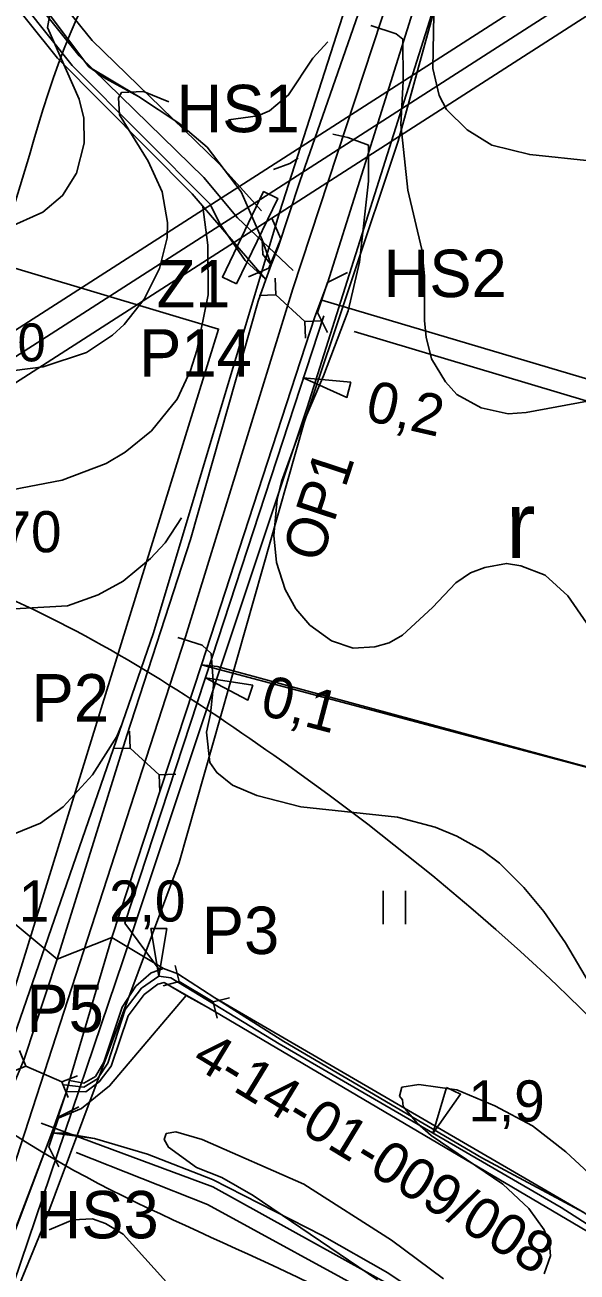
# Model space of a CAD drawing. Extents: x -684583 to -680383, y -1157874 to -1154904.
# Drawn here: x -682753.2 to -682578.4, y -1156107.3 to -1155712.7 of the extents above; entities that cross this region are included whole.
import ezdxf

# ---------------------------------------------------------------- set-up
doc = ezdxf.new("R2010")
doc.units = 0
for name, color, linetype in [('01_DOPRAVA', 7, 'Continuous'), ('01_VRSTEVNICE', 7, 'Continuous'), ('02_KULTURY STAV', 7, 'Continuous'), ('03_PC_NÁVRH', 7, 'Continuous'), ('03_PC_OBJEKTY_NÁVRH', 7, 'Continuous'), ('03_PC_OBJEKTY_STAV', 7, 'Continuous'), ('03_PC_STAV', 7, 'Continuous'), ('05_VHO_MELIORACE', 7, 'Continuous'), ('05_VHO_PŘÍKOP_NÁVRH', 7, 'Continuous'), ('05_VHO_V_TOK', 7, 'Continuous'), ('06_BIOGEOGRAFIE', 7, 'Continuous'), ('06_ÚSES_IP', 7, 'Continuous'), ('07_ELEKTRO', 7, 'Continuous'), ('07_OCH_P A POPISY TI', 7, 'Continuous')]:
    doc.layers.add(name, color=color, linetype=linetype)

msp = doc.modelspace()

# ---------------------------------------------------------------- linework, layer by layer
at = {"layer": '01_DOPRAVA'}
msp.add_lwpolyline([(-682444.78, -1155001.44), (-682484.97, -1155081.41), (-682523.81, -1155212.27), (-682554.69, -1155333.36), (-682575.58, -1155465.36), (-682603.29, -1155587.36), (-682620.55, -1155650.97), (-682668.34, -1155796.22), (-682702.3, -1155906.34), (-682764.53, -1156097.63), (-682782.62, -1156147.93)], dxfattribs=at)
at = {"layer": '01_VRSTEVNICE'}
for points in [[(-682382.21, -1155809.3), (-682389.33, -1155809.04), (-682397.32, -1155806.76), (-682406.03, -1155802.05), (-682410.45, -1155798.77), (-682430.27, -1155780.8), (-682439.26, -1155774.38), (-682444.11, -1155771.67), (-682453.53, -1155768.39), (-682461.51, -1155767.53), (-682469.5, -1155768.1), (-682506.59, -1155773.81), (-682523.13, -1155773.24), (-682535.12, -1155769.96), (-682551.95, -1155762.25), (-682565.36, -1155757.69), (-682573.35, -1155755.83), (-682593.32, -1155753.7), (-682605.3, -1155750.7), (-682613.14, -1155745.85), (-682619.7, -1155739.43), (-682621.99, -1155735.01), (-682623.98, -1155726.45), (-682623.41, -1155691.93)], [(-682985.16, -1155828.73), (-682971.04, -1155827.87), (-682959.05, -1155826.3), (-682925.39, -1155819.46), (-682916.83, -1155817.03), (-682906.56, -1155813.18), (-682896.29, -1155808.19), (-682880.89, -1155802.34), (-682838.09, -1155789.07), (-682808.99, -1155783.08), (-682772.76, -1155779.8), (-682758.78, -1155776.95), (-682747.51, -1155771.95), (-682741.24, -1155766.68), (-682736.82, -1155759.54), (-682734.39, -1155750.13), (-682734.53, -1155742.14), (-682735.96, -1155736.15), (-682746.07, -1155713.51), (-682745.09, -1155708.19)], [(-682643.67, -1155712.9), (-682635.68, -1155715.47), (-682633.54, -1155717.18), (-682633.4, -1155730.45), (-682634.11, -1155744.14), (-682631.97, -1155764.96), (-682627.55, -1155783.79), (-682626.69, -1155792.07), (-682626.69, -1155806.33), (-682626.12, -1155811.47), (-682624.41, -1155818.31), (-682619.99, -1155825.59), (-682616.42, -1155829.58), (-682608.72, -1155833.86), (-682600.16, -1155835.72), (-682594.46, -1155835.29), (-682575.06, -1155831.72)], [(-682657.28, -1155718.07), (-682662.01, -1155723.22), (-682669.72, -1155734.85), (-682675.76, -1155739.86), (-682679.47, -1155741.43), (-682688.74, -1155742.71)], [(-682707.57, -1155737.05), (-682715.6, -1155733.76), (-682722.55, -1155734.01), (-682723.55, -1155735.72), (-682723.26, -1155741.14), (-682714.14, -1155755.84), (-682709.71, -1155765.54), (-682708, -1155775.24), (-682708.14, -1155780.08), (-682710.57, -1155789.78), (-682715.42, -1155799.48), (-682721.7, -1155807.47), (-682725.4, -1155810.9), (-682733.68, -1155816.32), (-682747.37, -1155820.88), (-682756.5, -1155822.02)], [(-682655.65, -1155747.28), (-682650.94, -1155748.28), (-682644.38, -1155750.7), (-682644.38, -1155762.11), (-682647.23, -1155787.79), (-682650.8, -1155803.19), (-682658.65, -1155823.73), (-682666.35, -1155841.71), (-682671.91, -1155857.11), (-682673.34, -1155862.82), (-682674.34, -1155874.23), (-682673.48, -1155882.79), (-682670.77, -1155891.35), (-682667.35, -1155897.48), (-682662.93, -1155902.62), (-682656.08, -1155907.61), (-682649.23, -1155909.89), (-682642.39, -1155909.46), (-682637.82, -1155908.18), (-682633.68, -1155905.75), (-682624.13, -1155897.05), (-682616.71, -1155889.21), (-682612.15, -1155886.07), (-682607.58, -1155884.36), (-682600.73, -1155883.07), (-682596.17, -1155883.79), (-682588.47, -1155886.78), (-682581.33, -1155893.34), (-682575.34, -1155901.9)], [(-682666.67, -1155754.8), (-682669.34, -1155756.55), (-682674.48, -1155758.4)], [(-682757.36, -1155859.82), (-682741.38, -1155856.68), (-682727.4, -1155851.41), (-682721.41, -1155847.84), (-682713.14, -1155841.14), (-682705.01, -1155831.15), (-682700.73, -1155822.02), (-682698.73, -1155815.75), (-682695.16, -1155798.06), (-682695.31, -1155782.37), (-682696.88, -1155770.24)], [(-682862.77, -1155969.37), (-682865.91, -1155959.82), (-682870.76, -1155950.69), (-682885.88, -1155927.29), (-682908.84, -1155897.62), (-682911.55, -1155892.2), (-682911.55, -1155890.63), (-682910.7, -1155890.63), (-682910.56, -1155889.78), (-682891.16, -1155891.21), (-682875.47, -1155893.34), (-682852.93, -1155897.91), (-682834.1, -1155903.04), (-682825.54, -1155904.33), (-682809.56, -1155905.33), (-682793.59, -1155904.47), (-682787.88, -1155903.61), (-682767.91, -1155898.05), (-682739.67, -1155896.48), (-682729.97, -1155893.06), (-682722.12, -1155888.64), (-682713.42, -1155881.5), (-682708.82, -1155876.58), (-682703.58, -1155868.67)], [(-682704.72, -1155906.47), (-682697.02, -1155908.89), (-682694.17, -1155911.6), (-682693.45, -1155921.59), (-682694.45, -1155930.72), (-682695.73, -1155936.42), (-682694.59, -1155946.12), (-682692.45, -1155949.26), (-682687.46, -1155953.25), (-682679.76, -1155956.53), (-682665.78, -1155960.1), (-682635.25, -1155963.38), (-682623.27, -1155966.52), (-682616.42, -1155969.37), (-682608.29, -1155973.94), (-682602.87, -1155977.93), (-682595.17, -1155985.63), (-682588.89, -1155993.2), (-682582.05, -1156003.18), (-682561.93, -1156037.13)], [(-682763.92, -1156063.23), (-682764.06, -1156057.96), (-682766.06, -1156044.26), (-682769.62, -1156032.85), (-682773.76, -1156023.72), (-682787.31, -1156000.9), (-682797.01, -1155982.78), (-682797.15, -1155979.22), (-682791.31, -1155981.93), (-682785.17, -1155983.35), (-682781.18, -1155981.5), (-682778.18, -1155975.36), (-682778.47, -1155968.66), (-682779.32, -1155966.81), (-682779.85, -1155960.09), (-682769.48, -1155967.38), (-682763.92, -1155969.23), (-682756.79, -1155968.8), (-682748.23, -1155965.24), (-682741.09, -1155960.1), (-682731.82, -1155949.97), (-682724.12, -1155937.85), (-682722.55, -1155934.28)], [(-682588.75, -1156107.88), (-682586.75, -1156102.17), (-682587.04, -1156098.47), (-682588.75, -1156093.9), (-682593.6, -1156087.2), (-682601.88, -1156079.49), (-682624.55, -1156064.09), (-682628.98, -1156060.24), (-682633.4, -1156054.96), (-682633.68, -1156052.82), (-682634.54, -1156051.68), (-682633.83, -1156048.83), (-682628.41, -1156047.97), (-682616.42, -1156049.68), (-682604.44, -1156054.67), (-682592.46, -1156061.09), (-682581.9, -1156069.22), (-682561.65, -1156088.05)], [(-682641.53, -1156109.73), (-682680.9, -1156083.06), (-682690.88, -1156077.35), (-682698.87, -1156074.22), (-682707.72, -1156067.8), (-682709.14, -1156065.37), (-682708.43, -1156063.52), (-682705.43, -1156062.95), (-682697.02, -1156065.37), (-682664.92, -1156079.49), (-682637.11, -1156097.18), (-682620.7, -1156109.45)], [(-682745.52, -1156093.9), (-682737.96, -1156090.76), (-682731.82, -1156090.48), (-682727.69, -1156091.9), (-682722.12, -1156095.33), (-682705.43, -1156113.73), (-682691.17, -1156131.28), (-682682.47, -1156143.26), (-682670.49, -1156161.66), (-682629.69, -1156229.13), (-682597.45, -1156287.18), (-682585.33, -1156306.3), (-682572.83, -1156324.37)]]:
    msp.add_lwpolyline(points, dxfattribs=at)
at = {"layer": '02_KULTURY STAV'}
for points in [[(-682742.95, -1156008.33), (-682720.91, -1155937.51), (-682700.78, -1155875.54), (-682679.31, -1155800.06), (-682676.88, -1155793.28), (-682675.23, -1155788.62), (-682672.99, -1155782.95), (-682666.12, -1155762.26), (-682647.64, -1155709.29), (-682624.39, -1155632.23), (-682608.85, -1155568.57), (-682588.52, -1155559.14), (-682606.64, -1155634.44), (-682625.87, -1155693.99), (-682647.1, -1155761.89), (-682657.41, -1155794.38), (-682661.35, -1155805), (-682697.27, -1155915.21), (-682725.67, -1156001.43)], [(-682692.35, -1155915.71), (-682546.41, -1155955.28), (-682554.4, -1155990.65), (-682555.92, -1156043.51), (-682562.23, -1156060.24), (-682562.06, -1156068.8), (-682556.56, -1156078.19), (-682554.09, -1156081.55), (-682562.72, -1156088), (-682571.24, -1156092.01), (-682576.25, -1156088.48), (-682608.5, -1156071.15), (-682671.25, -1156034.36), (-682693.08, -1156020.51), (-682704.73, -1156012.95), (-682709.29, -1156011.25), (-682725.67, -1156001.43), (-682697.27, -1155915.21)], [(-682725.67, -1156001.43), (-682709.29, -1156011.25), (-682713.21, -1156012.6), (-682718.03, -1156016.89), (-682722.37, -1156023.45), (-682728.14, -1156040.85), (-682730.88, -1156045.44), (-682734.55, -1156047.54), (-682739.11, -1156046.65)], [(-682740.04, -1156050.18), (-682733.84, -1156050.25), (-682729.64, -1156047.08), (-682725.87, -1156042.18), (-682720.5, -1156026.23), (-682715.37, -1156019.5), (-682711.09, -1156016.18), (-682709.08, -1156015.71), (-682702.07, -1156019.82), (-682726.38, -1156048.39), (-682735.27, -1156055.51), (-682742.82, -1156058.77)]]:
    msp.add_lwpolyline(points, close=True, dxfattribs=at)
for points in [[(-682790.82, -1155659.69), (-682738.18, -1155725.49), (-682694.52, -1155769.41), (-682691.48, -1155775.66), (-682683.47, -1155787.27), (-682676.88, -1155793.28), (-682675.23, -1155788.62), (-682678.08, -1155780.69), (-682684.73, -1155765.47), (-682695.46, -1155751.36), (-682704.47, -1155743.75), (-682717.26, -1155735.33), (-682727.64, -1155729.6), (-682732.92, -1155725.98), (-682761.91, -1155687.44)], [(-682790.82, -1155659.69), (-682738.18, -1155725.49), (-682694.52, -1155769.41), (-682691.48, -1155775.66), (-682683.47, -1155787.27), (-682676.88, -1155793.28), (-682679.31, -1155800.06), (-682700.78, -1155875.54), (-682720.91, -1155937.51), (-682742.95, -1156008.33), (-682780.55, -1155977.07)], [(-682415.34, -1155677.48), (-682425.43, -1155731.81), (-682370.95, -1155762.69), (-682382.94, -1155812.42), (-682392.09, -1155851.75), (-682394.33, -1155862.14), (-682395.58, -1155865.96), (-682409.73, -1155861.86), (-682426.71, -1155857.66), (-682455.64, -1155852.31), (-682472.04, -1155850.36), (-682483.37, -1155850.15), (-682508.9, -1155844.44), (-682515.71, -1155860.72), (-682519, -1155873.01), (-682541.61, -1155930.68), (-682546.41, -1155955.28), (-682697.27, -1155915.21), (-682661.35, -1155805), (-682657.41, -1155794.38), (-682647.1, -1155761.89), (-682625.87, -1155693.99)], [(-682761.91, -1155687.44), (-682732.92, -1155725.98), (-682717.26, -1155735.33), (-682704.47, -1155743.75), (-682695.46, -1155751.36), (-682684.73, -1155765.47), (-682678.08, -1155780.69), (-682677.83, -1155785.3), (-682675.23, -1155788.62), (-682672.99, -1155782.95), (-682666.12, -1155762.26), (-682647.64, -1155709.29)], [(-682780.55, -1155977.07), (-682742.95, -1156008.33), (-682753.41, -1156039.97)], [(-682639.73, -1155986.71), (-682639.73, -1155997.21)], [(-682632.73, -1155986.71), (-682632.73, -1155997.21)], [(-682866.04, -1156320.76), (-682848.78, -1156285.62), (-682834.97, -1156248.66), (-682815.59, -1156196.79), (-682810.04, -1156179.89), (-682785.78, -1156122.22), (-682776.79, -1156103.44), (-682762.11, -1156061.38), (-682758.74, -1156052.65), (-682753.41, -1156039.97), (-682742.95, -1156008.33), (-682725.67, -1156001.43), (-682739.11, -1156046.65), (-682740.04, -1156050.18), (-682744.64, -1156063.3), (-682765.72, -1156119.15), (-682779.93, -1156155.81), (-682782.44, -1156169.94), (-682798.74, -1156209.36), (-682837.34, -1156293.13), (-682860.97, -1156340.11)], [(-682576.25, -1156088.48), (-682693.08, -1156020.51), (-682704.73, -1156012.95), (-682709.29, -1156011.25), (-682713.21, -1156012.6), (-682718.03, -1156016.89), (-682722.37, -1156023.45), (-682728.14, -1156040.85), (-682730.88, -1156045.44), (-682734.55, -1156047.54), (-682739.11, -1156046.65), (-682740.04, -1156050.18), (-682733.84, -1156050.25), (-682729.64, -1156047.08), (-682725.87, -1156042.18), (-682720.5, -1156026.23), (-682715.37, -1156019.5), (-682711.09, -1156016.18), (-682709.08, -1156015.71), (-682706.58, -1156017.12), (-682695.09, -1156023.72), (-682560.35, -1156103.1)], [(-682569.3, -1156156.35), (-682580.04, -1156146.44), (-682601.47, -1156130.49), (-682600.97, -1156121.96), (-682616.85, -1156113.92), (-682624.62, -1156116.74), (-682638.27, -1156107.54), (-682659.05, -1156095.72), (-682693.74, -1156078.06), (-682714.33, -1156069.98), (-682731.17, -1156065.1), (-682744.64, -1156063.3), (-682742.82, -1156058.77), (-682735.27, -1156055.51), (-682726.38, -1156048.39), (-682702.07, -1156019.82), (-682695.09, -1156023.72), (-682560.35, -1156103.1)], [(-682596.72, -1156380.07), (-682557.32, -1156288.22), (-682537.57, -1156239.43), (-682529.35, -1156221.47), (-682529.35, -1156221.47), (-682525.25, -1156214.91), (-682536.68, -1156197.77), (-682569.3, -1156156.35), (-682580.04, -1156146.44), (-682601.47, -1156130.49), (-682624.62, -1156116.74), (-682638.27, -1156107.54), (-682659.05, -1156095.72), (-682693.74, -1156078.06), (-682714.33, -1156069.98), (-682731.17, -1156065.1), (-682740.76, -1156063.41), (-682744.64, -1156063.3), (-682779.93, -1156155.81), (-682782.44, -1156169.94), (-682798.74, -1156209.36), (-682837.34, -1156293.13), (-682860.97, -1156340.11)]]:
    msp.add_lwpolyline(points, dxfattribs=at)
at = {"layer": '03_PC_NÁVRH'}
for points in [[(-682659.15, -1155799.78), (-682508.9, -1155844.44), (-682478.39, -1155849.54), (-682459.54, -1155849.54), (-682394.36, -1155864.99)], [(-682748.06, -1156060.15), (-682693.66, -1156080.3), (-682637.14, -1156111.72), (-682584.4, -1156145.39), (-682568.41, -1156161.75), (-682527.4, -1156217.35)]]:
    msp.add_lwpolyline(points, dxfattribs=at)
at = {"layer": '03_PC_OBJEKTY_NÁVRH'}
for points in [[(-682988.48, -1155429.24), (-682918.93, -1155468.13), (-682893.72, -1155488.38), (-682865.08, -1155528.33), (-682817.78, -1155611.5), (-682731.85, -1155717.62), (-682691.81, -1155756.51), (-682678.23, -1155771.5)], [(-682993.86, -1155439.08), (-682925.02, -1155478.67), (-682901.14, -1155497.18), (-682874.68, -1155534.19), (-682826.68, -1155618.76), (-682742.86, -1155723.24), (-682700.24, -1155766.11), (-682676.88, -1155793.28)], [(-682686.14, -1155794.63), (-682690.64, -1155792.46), (-682677.62, -1155765.43), (-682673.12, -1155767.6), (-682686.14, -1155794.63)], [(-682673.99, -1155792.77), (-682673.75, -1155798.07), (-682679.05, -1155798.31)], [(-682673.75, -1155798.07), (-682664.52, -1155806.5)], [(-682659.23, -1155806.27), (-682664.52, -1155806.5), (-682664.29, -1155811.8)], [(-682400.75, -1155870.09), (-682458.37, -1155856.77), (-682478.51, -1155856.77), (-682510.12, -1155851.15), (-682648.97, -1155809.69)], [(-682540.56, -1156208.64), (-682574.04, -1156165.3), (-682587.85, -1156149.61), (-682639.37, -1156116.57), (-682695.33, -1156085.89), (-682737, -1156069.49)]]:
    msp.add_lwpolyline(points, dxfattribs=at)
at = {"layer": '03_PC_OBJEKTY_STAV'}
for points in [[(-682674.99, -1155773.83), (-682672.19, -1155780.32), (-682675.9, -1155789.61), (-682682.39, -1155792.4)], [(-682657.33, -1155810.03), (-682660.49, -1155803.7), (-682657.33, -1155794.22), (-682651, -1155791.06)], [(-682720.02, -1155936.19), (-682719.83, -1155941.49), (-682725.13, -1155941.67)], [(-682719.83, -1155941.49), (-682710.68, -1155950)], [(-682705.38, -1155949.81), (-682710.68, -1155950), (-682710.49, -1155955.3)], [(-682705.58, -1156010.28), (-682704.29, -1156015.42), (-682709.43, -1156016.72)], [(-682704.29, -1156015.42), (-682693.55, -1156021.83)], [(-682688.41, -1156020.53), (-682693.55, -1156021.83), (-682692.26, -1156026.97)], [(-682754.88, -1156037.24), (-682752.93, -1156042.17), (-682757.87, -1156044.12)], [(-682752.93, -1156042.17), (-682741.47, -1156047.15)], [(-682736.53, -1156045.2), (-682741.47, -1156047.15), (-682739.52, -1156052.08)], [(-682742.41, -1156073.99), (-682745.57, -1156067.67), (-682742.41, -1156058.18), (-682736.08, -1156055.02)]]:
    msp.add_lwpolyline(points, dxfattribs=at)
at = {"layer": '03_PC_STAV'}
msp.add_lwpolyline([(-682668.28, -1155790.37), (-682685.83, -1155773.73), (-682696.52, -1155760.91), (-682735.97, -1155722.42), (-682821.6, -1155615.88), (-682870.86, -1155529.79), (-682895.8, -1155493.35), (-682921.9, -1155473.38), (-683004.74, -1155425.7)], dxfattribs=at)
at = {"layer": '05_VHO_MELIORACE'}
for p, q in [((-682635.04, -1155749.47), (-682580.41, -1155551.03)), ((-682664.8, -1155838.52), (-682635.04, -1155749.47)), ((-682704.39, -1155977.74), (-682664.8, -1155838.52)), ((-682747.8, -1156093.97), (-682704.39, -1155977.74)), ((-682772.31, -1156153.49), (-682747.8, -1156093.97))]:
    msp.add_line(p, q, dxfattribs=at)
msp.add_lwpolyline([(-682427.32, -1155652.04), (-682442.64, -1155733.79), (-682379.89, -1155766.86), (-682399.94, -1155848.22), (-682465.23, -1155827.02), (-682513.91, -1155819), (-682556.29, -1155928.43), (-682568.9, -1156017.02), (-682570.04, -1156062.28), (-682551.72, -1156093.79), (-682504.18, -1156161.97), (-682541.38, -1156231.07), (-682567.04, -1156285.02), (-682772.31, -1156153.49), (-682747.8, -1156093.97), (-682704.39, -1155977.74), (-682664.8, -1155838.52), (-682635.04, -1155749.47), (-682580.41, -1155551.03)], dxfattribs=at)
msp.add_lwpolyline([(-683016.49, -1155781.73), (-682936.04, -1155794.17), (-682848.83, -1155761.96), (-682691.86, -1155808.93), (-682793.99, -1156138.37), (-682858.18, -1156098.46), (-682817.93, -1155910.57), (-682879.64, -1155866.28), (-683019.17, -1155809.91)], close=True, dxfattribs=at)
at = {"layer": '05_VHO_PŘÍKOP_NÁVRH'}
msp.add_lwpolyline([(-682658.52, -1155804.75), (-682693.9, -1155912.7), (-682721.49, -1155996.87), (-682710.7, -1156011.52)], dxfattribs=at)
at = {"layer": '05_VHO_V_TOK'}
for points in [[(-682649.95, -1155825.72), (-682651.21, -1155830.56), (-682665.1, -1155824.38)], [(-682681.02, -1155921.59), (-682682.59, -1155926.34), (-682696.04, -1155919.24)], [(-682713.27, -1155998.63), (-682708.27, -1155998.63), (-682710.77, -1156013.63)], [(-682619.73, -1156048.86), (-682615.23, -1156051.04), (-682624.02, -1156063.45)]]:
    msp.add_lwpolyline(points, close=True, dxfattribs=at)
msp.add_lwpolyline([(-682740.74, -1156048.05), (-682734.56, -1156048.85), (-682730.18, -1156046.18), (-682726.95, -1156041.18), (-682721.44, -1156024.25), (-682716.22, -1156017.49), (-682710.77, -1156013.63), (-682706.96, -1156014.25), (-682672.72, -1156035.1), (-682583.35, -1156086.9), (-682554.85, -1156105.08), (-682548.26, -1156112.47), (-682512.95, -1156161.54), (-682502.95, -1156178.81)], dxfattribs=at)
at = {"layer": '06_BIOGEOGRAFIE'}
for points in [[(-682624.87, -1154935.44), (-682669.05, -1155140.04), (-682739.65, -1155253.72), (-682834.36, -1155382.91), (-682941.12, -1155661.96), (-683008.28, -1155760.14), (-683056.49, -1155810.09), (-683084.04, -1155808.37), (-683154.45, -1155886.49), (-683231.94, -1156062.19), (-683280.08, -1156211.64), (-683362.74, -1156430.39), (-683497.05, -1156731.83), (-683541.82, -1156781.78), (-683638.25, -1156792.12), (-683701.96, -1156768), (-683817.33, -1156693.94)], [(-682856.86, -1155847.34), (-682791.42, -1155830.12), (-682727.71, -1155694.04), (-682681.22, -1155649.25), (-682596.84, -1155571.74), (-682571.01, -1155502.84), (-682602.01, -1155421.88), (-682614.06, -1155356.43), (-682565.85, -1155299.59), (-682515.91, -1155292.7)], [(-682538.3, -1156231.46), (-682619.23, -1156136.72), (-682741.49, -1156072.99), (-682905.07, -1155940.36), (-683017, -1155857.68), (-683037.66, -1155826.67), (-683017, -1155811.17), (-682820.7, -1155868.01), (-682758.71, -1155893.85), (-682674.33, -1155943.8), (-682548.63, -1156054.04), (-682459.09, -1156176.34)]]:
    msp.add_spline(points, degree=3, dxfattribs=at)
at = {"layer": '06_ÚSES_IP'}
for points in [[(-682530.18, -1155187.74), (-682556.31, -1155287.32), (-682580.65, -1155417.4), (-682596.62, -1155505.37), (-682619.02, -1155596.96), (-682637.3, -1155662.36), (-682672.55, -1155772.07), (-682712.43, -1155905.02), (-682772.45, -1156078.06), (-682846.1, -1156262.2), (-682899.06, -1156383.28), (-682928.82, -1156472.07), (-682968.71, -1156622.54), (-683017.6, -1156838.34)], [(-683045.5, -1156945.1), (-682993.87, -1156850.83), (-682970.35, -1156763.63), (-682943.14, -1156635.49), (-682907.69, -1156485.87), (-682877.43, -1156403.71), (-682855.81, -1156343.74), (-682797.01, -1156219.49), (-682773.09, -1156158.67), (-682722.07, -1156008.47), (-682663.84, -1155833.77), (-682598.99, -1155629.09), (-682554.6, -1155429.31), (-682533.56, -1155299)]]:
    msp.add_lwpolyline(points, dxfattribs=at)
at = {"layer": '07_ELEKTRO'}
msp.add_lwpolyline([(-683353.35, -1157770.3), (-683109.07, -1157109.08), (-683073.5, -1157019.42), (-683054.68, -1156978.22), (-683011.49, -1156911.63), (-683020.57, -1156816.29), (-682818.44, -1155857.57), (-682314.17, -1155533.82)], dxfattribs=at)
msp.add_lwpolyline([(-683353.35, -1157770.3), (-683109.07, -1157109.08), (-683073.5, -1157019.42), (-683054.68, -1156978.22), (-683011.49, -1156911.63), (-683020.57, -1156816.29), (-682818.44, -1155857.57), (-682314.17, -1155533.82)], dxfattribs=at)
at = {"layer": '07_OCH_P A POPISY TI'}
for p, q in [((-682820.07, -1155850.3), (-682317.95, -1155527.93)), ((-682310.39, -1155539.71), (-682812.19, -1155861.88))]:
    msp.add_line(p, q, dxfattribs=at)

# ---------------------------------------------------------------- texts
at = {"layer": '01_VRSTEVNICE'}
msp.add_text('520', height=12, dxfattribs=at).set_placement((-682773.37, -1155819.14))
at = {"layer": '02_KULTURY STAV'}
msp.add_text('r', height=21, dxfattribs=at).set_placement((-682600.85, -1155881.38))
at = {"layer": '03_PC_OBJEKTY_NÁVRH'}
for s, p in [('Z1', (-682711.49, -1155802.07)), ('P14', (-682717.01, -1155823.97))]:
    msp.add_text(s, height=15, dxfattribs=at).set_placement(p)
at = {"layer": '03_PC_OBJEKTY_STAV'}
for s, p in [('HS1', (-682705.19, -1155746.63)), ('HS2', (-682639.64, -1155798.8)), ('P2', (-682751.06, -1155933.1)), ('P3', (-682697.18, -1156006.68)), ('P5', (-682752.72, -1156031.37)), ('HS3', (-682749.83, -1156096.65))]:
    msp.add_text(s, height=15, dxfattribs=at).set_placement(p)
at = {"layer": '05_VHO_MELIORACE'}
msp.add_text('1970', height=13, dxfattribs=at).set_placement((-682780.26, -1155879.54))
at = {"layer": '05_VHO_PŘÍKOP_NÁVRH'}
msp.add_text('OP1', height=13, rotation=71.8514, dxfattribs=at).set_placement((-682659.55, -1155883.28))
at = {"layer": '05_VHO_V_TOK'}
for s, rotation, p in [('0,2', 347.0468, (-682645.88, -1155837.63)), ('0,1', 345.2532, (-682679.23, -1155930.74)), ('4-14-01-009/008', 328.6612, (-682700.9, -1156041.66))]:
    msp.add_text(s, height=13, rotation=rotation, dxfattribs=at).set_placement(p)
for s, p in [('2,1', (-682769.59, -1155996.4)), ('2,0', (-682726.53, -1155996.4)), ('1,9', (-682612.77, -1156059.65))]:
    msp.add_text(s, height=13, dxfattribs=at).set_placement(p)

doc.saveas('drawing.dxf')
